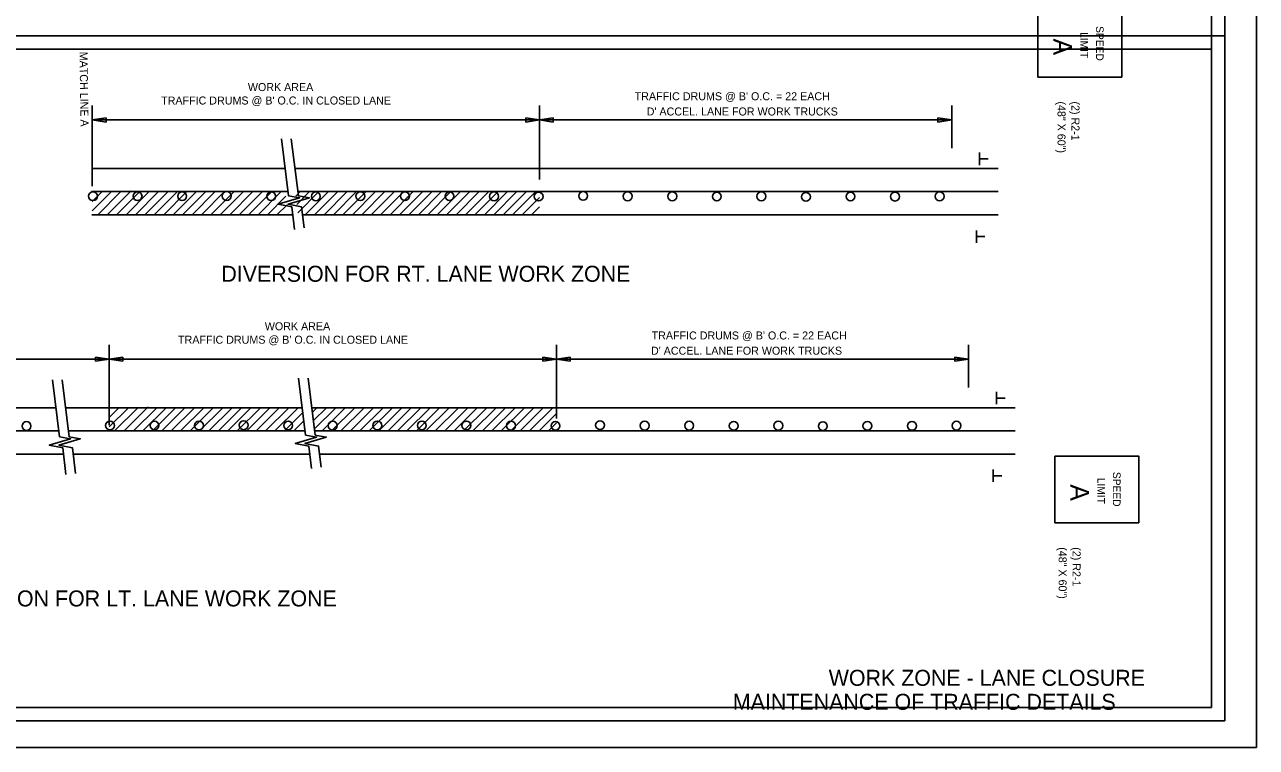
# Model space of a CAD drawing. Extents: x 13528 to 25043, y 7635 to 10612.
# Drawn here: x 16297 to 17221, y 9545 to 10087 of the extents above; entities that cross this region are included whole.
import ezdxf

# ---------------------------------------------------------------- set-up
doc = ezdxf.new("R2010")
doc.units = 0
for name, color, linetype in [('Default', 7, 'Continuous'), ('R_Border Plan-Plan', 7, 'Continuous'), ('R_Draft', 7, 'Continuous'), ('R_Revision Date Text', 7, 'Continuous')]:
    doc.layers.add(name, color=color, linetype=linetype)

msp = doc.modelspace()

# ---------------------------------------------------------------- linework, layer by layer
at = {"layer": 'Default'}
for p, q in [((16347.66, 10026.2), (16347.66, 9965.85)), ((16683.01, 10026.2), (16683.01, 9970.85)), ((16992.11, 10026.2), (16992.11, 9994.29)), ((16347.66, 10015.42), (16357.96, 10016.96)), ((16347.66, 10016.89), (16347.66, 9965.85)), ((16347.66, 10016.89), (16347.66, 9965.85)), ((16347.66, 10016.89), (16347.66, 9965.85)), ((16683.01, 10015.42), (16347.66, 10015.42)), ((16357.96, 10013.87), (16347.66, 10015.42)), ((16357.96, 10016.96), (16357.96, 10013.87)), ((16672.7, 10013.87), (16672.7, 10016.96)), ((16672.7, 10016.96), (16683.01, 10015.42)), ((16683.01, 10015.42), (16672.7, 10013.87)), ((16683.01, 10015.42), (16693.31, 10016.96)), ((16992.11, 10015.42), (16683.01, 10015.42)), ((16693.31, 10013.87), (16683.01, 10015.42)), ((16693.31, 10016.96), (16693.31, 10013.87)), ((16981.81, 10013.87), (16981.81, 10016.96)), ((16981.81, 10016.96), (16992.11, 10015.42)), ((16992.11, 10015.42), (16981.81, 10013.87)), ((17012.98, 9981.65), (17012.98, 9990.92)), ((17013.12, 9986.26), (17019.45, 9986.26)), ((16347.66, 9979.04), (16492.44, 9979.04)), ((16499.62, 9979.04), (16683.01, 9979.04)), ((16683.01, 9979.04), (17026.9, 9979.04)), ((16346.96, 9961.66), (16493.88, 9961.66)), ((16347.66, 9947.27), (16362.06, 9961.66)), ((16347.66, 9954.34), (16354.99, 9961.66)), ((16351.75, 9944.28), (16369.13, 9961.66)), ((16358.82, 9944.28), (16376.75, 9962.21)), ((16365.89, 9944.28), (16383.27, 9961.66)), ((16372.96, 9944.28), (16390.34, 9961.66)), ((16380.03, 9944.28), (16397.41, 9961.66)), ((16387.1, 9944.28), (16404.48, 9961.66)), ((16394.17, 9944.28), (16411.55, 9961.66)), ((16401.24, 9944.28), (16418.63, 9961.66)), ((16408.31, 9944.28), (16425.7, 9961.66)), ((16415.38, 9944.28), (16432.77, 9961.66)), ((16422.46, 9944.28), (16439.84, 9961.66)), ((16429.53, 9944.28), (16446.91, 9961.66)), ((16436.6, 9944.28), (16453.98, 9961.66)), ((16443.67, 9944.28), (16461.05, 9961.66)), ((16450.74, 9944.28), (16468.12, 9961.66)), ((16457.81, 9944.28), (16475.19, 9961.66)), ((16464.88, 9944.28), (16482.27, 9961.66)), ((16471.95, 9944.28), (16489.34, 9961.66)), ((16479.02, 9944.28), (16492.91, 9958.16)), ((16500.17, 9958.35), (16503.48, 9961.66)), ((16500.93, 9952.04), (16510.55, 9961.66)), ((16501.69, 9945.73), (16517.62, 9961.66)), ((16501.79, 9961.66), (16683.01, 9961.66)), ((16507.31, 9944.28), (16524.69, 9961.66)), ((16514.38, 9944.28), (16531.76, 9961.66)), ((16521.45, 9944.28), (16538.83, 9961.66)), ((16528.52, 9944.28), (16545.9, 9961.66)), ((16535.59, 9944.28), (16552.98, 9961.66)), ((16542.66, 9944.28), (16560.05, 9961.66)), ((16549.74, 9944.28), (16567.12, 9961.66)), ((16556.81, 9944.28), (16574.19, 9961.66)), ((16563.88, 9944.28), (16581.26, 9961.66)), ((16570.95, 9944.28), (16588.33, 9961.66)), ((16578.02, 9944.28), (16595.4, 9961.66)), ((16585.09, 9944.28), (16602.47, 9961.66)), ((16592.16, 9944.28), (16609.54, 9961.66)), ((16599.23, 9944.28), (16616.62, 9961.66)), ((16606.3, 9944.28), (16623.69, 9961.66)), ((16613.37, 9944.28), (16630.76, 9961.66)), ((16620.45, 9944.28), (16637.83, 9961.66)), ((16627.52, 9944.28), (16644.9, 9961.66)), ((16634.59, 9944.28), (16651.97, 9961.66)), ((16641.66, 9944.28), (16659.04, 9961.66)), ((16648.73, 9944.28), (16666.11, 9961.66)), ((16655.8, 9944.28), (16673.18, 9961.66)), ((16662.87, 9944.28), (16680.26, 9961.66)), ((16669.94, 9944.28), (16683.01, 9957.35)), ((16683.01, 9961.66), (17026.9, 9961.66)), ((16486.1, 9944.28), (16493.67, 9951.85)), ((16677.01, 9944.28), (16683.01, 9950.28)), ((16347.44, 9944.28), (16498.05, 9944.28)), ((16505.7, 9944.28), (16683.01, 9944.28)), ((16683.01, 9944.28), (17026.9, 9944.28)), ((17010.58, 9923.38), (17010.58, 9932.65)), ((17010.72, 9927.99), (17017.05, 9927.99)), ((16360.35, 9846.79), (16360.35, 9786.44)), ((16695.7, 9846.79), (16695.7, 9791.44)), ((17004.8, 9846.79), (17004.8, 9814.87)), ((16350.05, 9834.45), (16350.05, 9837.55)), ((16350.05, 9837.55), (16360.35, 9836)), ((16360.35, 9836), (16370.65, 9837.55)), ((16360.35, 9837.47), (16360.35, 9786.44)), ((16360.35, 9837.47), (16360.35, 9786.44)), ((16360.35, 9837.47), (16360.35, 9786.44)), ((16370.65, 9837.55), (16370.65, 9834.45)), ((16685.4, 9834.45), (16685.4, 9837.54)), ((16685.4, 9837.54), (16695.7, 9836)), ((16695.7, 9836), (16706, 9837.55)), ((16706, 9837.55), (16706, 9834.45)), ((16994.5, 9834.45), (16994.5, 9837.55)), ((16994.5, 9837.55), (17004.8, 9836)), ((16360.35, 9836), (16051.25, 9836)), ((16360.35, 9836), (16350.05, 9834.45)), ((16695.7, 9836), (16360.35, 9836)), ((16370.65, 9834.45), (16360.35, 9836)), ((16695.7, 9836), (16685.4, 9834.45)), ((17004.8, 9836), (16695.7, 9836)), ((16706, 9834.45), (16695.7, 9836)), ((17004.8, 9836), (16994.5, 9834.45)), ((17025.67, 9802.23), (17025.67, 9811.51)), ((16051.44, 9799.63), (16320.37, 9799.63)), ((16327.66, 9799.63), (16360.35, 9799.63)), ((16360.35, 9799.63), (16505.13, 9799.63)), ((16360.35, 9785.23), (16374.74, 9799.63)), ((16360.35, 9792.3), (16367.67, 9799.63)), ((16364.43, 9782.24), (16381.81, 9799.63)), ((16371.5, 9782.24), (16389.44, 9800.18)), ((16378.57, 9782.24), (16395.96, 9799.63)), ((16385.64, 9782.24), (16403.03, 9799.63)), ((16392.72, 9782.24), (16410.1, 9799.63)), ((16399.79, 9782.24), (16417.17, 9799.63)), ((16406.86, 9782.24), (16424.24, 9799.63)), ((16413.93, 9782.24), (16431.31, 9799.63)), ((16421, 9782.24), (16438.38, 9799.63)), ((16428.07, 9782.24), (16445.45, 9799.63)), ((16435.14, 9782.24), (16452.52, 9799.63)), ((16442.21, 9782.24), (16459.6, 9799.63)), ((16449.28, 9782.24), (16466.67, 9799.63)), ((16456.36, 9782.24), (16473.74, 9799.63)), ((16463.43, 9782.24), (16480.81, 9799.63)), ((16470.5, 9782.24), (16487.88, 9799.63)), ((16477.57, 9782.24), (16494.95, 9799.63)), ((16484.64, 9782.24), (16502.02, 9799.63)), ((16512.31, 9799.63), (16695.7, 9799.63)), ((16512.86, 9796.32), (16516.16, 9799.63)), ((16513.62, 9790.01), (16523.24, 9799.63)), ((16514.38, 9783.69), (16530.31, 9799.63)), ((16519.99, 9782.24), (16537.38, 9799.63)), ((16527.07, 9782.24), (16544.45, 9799.63)), ((16534.14, 9782.24), (16551.52, 9799.63)), ((16541.21, 9782.24), (16558.59, 9799.63)), ((16548.28, 9782.24), (16565.66, 9799.63)), ((16555.35, 9782.24), (16572.73, 9799.63)), ((16562.42, 9782.24), (16579.8, 9799.63)), ((16569.49, 9782.24), (16586.88, 9799.63)), ((16576.56, 9782.24), (16593.95, 9799.63)), ((16583.63, 9782.24), (16601.02, 9799.63)), ((16590.71, 9782.24), (16608.09, 9799.63)), ((16597.78, 9782.24), (16615.16, 9799.63)), ((16604.85, 9782.24), (16622.23, 9799.63)), ((16611.92, 9782.24), (16629.3, 9799.63)), ((16618.99, 9782.24), (16636.37, 9799.63)), ((16626.06, 9782.24), (16643.44, 9799.63)), ((16633.13, 9782.24), (16650.51, 9799.63)), ((16640.2, 9782.24), (16657.59, 9799.63)), ((16647.27, 9782.24), (16664.66, 9799.63)), ((16654.35, 9782.24), (16671.73, 9799.63)), ((16661.42, 9782.24), (16678.8, 9799.63)), ((16668.49, 9782.24), (16685.87, 9799.63)), ((16675.56, 9782.24), (16692.94, 9799.63)), ((16695.7, 9799.63), (17039.59, 9799.63)), ((17025.81, 9806.85), (17032.14, 9806.85)), ((16491.71, 9782.24), (16505.6, 9796.13)), ((16682.63, 9782.24), (16695.7, 9795.31)), ((16050.54, 9782.24), (16322.55, 9782.24)), ((16329.83, 9782.24), (16359.65, 9782.24)), ((16359.65, 9782.24), (16506.58, 9782.24)), ((16498.78, 9782.24), (16506.36, 9789.82)), ((16514.48, 9782.24), (16695.7, 9782.24)), ((16689.7, 9782.24), (16695.7, 9788.24)), ((16695.7, 9782.24), (17039.59, 9782.24)), ((16051.03, 9764.86), (16326.09, 9764.86)), ((16333.38, 9764.86), (16360.13, 9764.86)), ((16360.13, 9764.86), (16510.74, 9764.86)), ((16518.39, 9764.86), (16695.7, 9764.86)), ((16695.7, 9764.86), (17039.59, 9764.86)), ((17023.27, 9743.96), (17023.27, 9753.24)), ((17023.41, 9748.58), (17029.74, 9748.58))]:
    msp.add_line(p, q, dxfattribs=at)
for points in [[(17119.77, 10047.61), (17056.74, 10047.61), (17056.74, 10097.61), (17119.77, 10097.61)], [(17132.46, 9713.27), (17069.44, 9713.27), (17069.44, 9763.27), (17132.46, 9763.27)]]:
    msp.add_lwpolyline(points, close=True, dxfattribs=at)
for points in [[(16489.56, 10001.26), (16494.9, 9958.5), (16503.16, 9957.05), (16487.13, 9952.19), (16497.33, 9950.24), (16499.36, 9933.39)], [(16496.85, 10001.26), (16502.19, 9958.5), (16510.44, 9957.05), (16494.42, 9952.19), (16504.62, 9950.24), (16506.52, 9934.44)], [(16317.76, 9820.57), (16323.1, 9777.81), (16331.36, 9776.35), (16315.33, 9771.5), (16325.53, 9769.55), (16327.94, 9749.48)], [(16325.04, 9820.57), (16330.38, 9777.81), (16338.64, 9776.35), (16322.61, 9771.5), (16332.81, 9769.55), (16335.12, 9750.35)], [(16502.25, 9821.84), (16507.59, 9779.09), (16515.85, 9777.63), (16499.82, 9772.77), (16510.02, 9770.83), (16512.05, 9753.98)], [(16509.54, 9821.84), (16514.88, 9779.09), (16523.13, 9777.63), (16507.11, 9772.77), (16517.31, 9770.83), (16519.21, 9755.02)]]:
    msp.add_lwpolyline(points, dxfattribs=at)
for centre in [(16348.21, 9958.24), (16381.62, 9958.24), (16415.03, 9958.25), (16448.44, 9958.45), (16481.85, 9958.24), (16515.27, 9958.13), (16548.68, 9958.29), (16582.09, 9958.29), (16615.5, 9958.29), (16648.91, 9958.13), (16682.32, 9958.01), (16715.73, 9958.49), (16749.14, 9958.17), (16782.55, 9958.17), (16815.96, 9958.01), (16849.37, 9958.14), (16882.78, 9957.79), (16916.19, 9958.01), (16949.6, 9957.98), (16983.01, 9958.14), (16298.36, 9785.85), (16360.9, 9786.26), (16394.31, 9786.26), (16427.72, 9786.27), (16461.14, 9786.47), (16494.55, 9786.26), (16527.96, 9786.15), (16561.37, 9786.31), (16594.78, 9786.31), (16628.19, 9786.31), (16661.6, 9786.16), (16695.01, 9786.03), (16728.42, 9786.51), (16761.83, 9786.19), (16795.24, 9786.19), (16828.65, 9786.03), (16862.06, 9786.17), (16895.47, 9785.81), (16928.88, 9786.03), (16962.29, 9786), (16995.7, 9786.16)]:
    msp.add_circle(centre, 3.33, dxfattribs=at)
at = {"layer": 'R_Border Plan-Plan'}
msp.add_line((15615.87, 10078.42), (17196.77, 10078.42), dxfattribs=at)
at = {"layer": 'R_Draft'}
for q in [(17196.77, 10592.07), (15615.87, 9564.77)]:
    msp.add_line((17196.77, 9564.77), q, dxfattribs=at)
at = {"layer": 'R_Revision Date Text'}
for points in [[(15553.84, 10611.55), (17220.54, 10611.55), (17220.54, 9544.86), (15553.84, 9544.86)], [(15625.87, 10582.07), (16873.57, 10582.07), (16873.57, 10532.67), (16961.27, 10532.67), (17081.77, 10532.67), (17081.77, 10421.01), (17186.77, 10421.01), (17186.77, 9574.77), (15625.87, 9574.77)], [(15625.87, 10068.42), (17186.77, 10068.42), (17186.77, 9574.77), (15625.87, 9574.77)]]:
    msp.add_lwpolyline(points, close=True, dxfattribs=at)

# ---------------------------------------------------------------- texts
at = {"layer": 'Default'}
for s, height, rotation, p in [('LIMIT', 5.729, 270, (17088.59, 10081.37)), ('SPEED', 5.729, 270, (17100.3, 10085.8)), ('A', 13.96, 270, (17068.37, 10076.52)), ('MATCH LINE A', 6, 270.80593, (16338.09, 10066.6)), ('(48" X 60")', 6, 270, (17071.44, 10029.32)), ('(2) R2-1', 6, 270, (17081.91, 10029.32)), ('LIMIT', 5.729, 270, (17101.28, 9747.03)), ('SPEED', 5.729, 270, (17112.99, 9751.46)), ('A', 13.96, 270, (17081.06, 9742.18)), ('(48" X 60")', 6, 270, (17072.28, 9694.98)), ('(2) R2-1', 6, 270, (17082.74, 9694.98))]:
    msp.add_text(s, height=height, rotation=rotation, dxfattribs=at).set_placement(p)
for s, height, p in [('WORK AREA', 6, (16464.33, 10037.11)), ("TRAFFIC DRUMS @ B' O.C. IN CLOSED LANE", 6, (16399.29, 10027.03)), ("TRAFFIC DRUMS @ B' O.C. = 22 EACH", 6, (16754.38, 10030.22)), ("D' ACCEL. LANE FOR WORK TRUCKS", 6, (16763.38, 10018.79)), ('DIVERSION FOR RT. LANE WORK ZONE', 12, (16444.47, 9894.07)), ('WORK AREA', 6, (16477.02, 9857.69)), ("TRAFFIC DRUMS @ B' O.C. = 22 EACH", 6, (16767.07, 9850.8)), ("TRAFFIC DRUMS @ B' O.C. IN CLOSED LANE", 6, (16411.98, 9847.61)), ("D' ACCEL. LANE FOR WORK TRUCKS", 6, (16766.59, 9839.37)), ('DIVERSION FOR LT. LANE WORK ZONE', 12, (16226.98, 9650.56))]:
    msp.add_text(s, height=height, dxfattribs=at).set_placement(p)
at = {"layer": 'R_Border Plan-Plan'}
for s, p in [('WORK ZONE - LANE CLOSURE', (16899.86, 9591.02)), ('MAINTENANCE OF TRAFFIC DETAILS', (16827.97, 9573.02))]:
    msp.add_text(s, height=12, dxfattribs=at).set_placement(p)

doc.saveas('drawing.dxf')
